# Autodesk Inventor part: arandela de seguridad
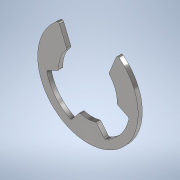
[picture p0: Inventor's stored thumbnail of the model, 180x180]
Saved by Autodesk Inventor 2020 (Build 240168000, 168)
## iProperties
Created: 2022-02
Part Number: arandela de seguridad
Material: Acero, alta resistencia, aleación baja
Document SubType Name: Modeling
Designer: Eresthor
Density: 7.85 g/cm^3
Appearance: Acero - Pulido
Author: Eresthor
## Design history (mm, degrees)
sketch "Boceto1"
  geometry: L1 (-1.903, -4.463)-(-1.083, -3.456); L2 (1.903, -4.463)-(1.083, -3.456); L3 (-2.549, 2.569)-(-3.401, 4.635); L4 (2.549, 2.569)-(3.401, 4.635); L5 (-4.775, -0.858)-(-3.61, -0.284); L6 (4.775, -0.858)-(3.61, -0.284); A1 r 6 centre (0, 0) between (-3.71, 4.715) and (3.71, 4.715); A2 r 3.5 centre (0, 0) between (-0.877, -3.388) and (0.877, -3.388); A3 r 3.5 centre (0, 0) between (3.499, -0.099) and (2.586, 2.358); A4 r 3.5 centre (0, 0) between (-2.586, 2.358) and (-3.499, -0.099); A5 r 5 centre (0, 0) between (2.143, -4.517) and (4.882, -1.081); A6 r 5 centre (0, 0) between (-4.882, -1.081) and (-2.143, -4.517); A7 r 0.2 centre (-3.586, 4.558) between (-3.401, 4.635) and (-3.71, 4.715); A8 r 0.2 centre (3.586, 4.558) between (3.71, 4.715) and (3.401, 4.635); A9 r 0.2 centre (2.734, 2.493) between (2.549, 2.569) and (2.586, 2.358); A10 r 0.2 centre (-2.734, 2.493) between (-2.586, 2.358) and (-2.549, 2.569); A11 r 0.2 centre (-3.699, -0.104) between (-3.61, -0.284) and (-3.499, -0.099); A12 r 0.2 centre (3.699, -0.104) between (3.499, -0.099) and (3.61, -0.284); A13 r 0.2 centre (4.687, -1.037) between (4.882, -1.081) and (4.775, -0.858); A14 r 0.2 centre (2.058, -4.337) between (1.903, -4.463) and (2.143, -4.517); A15 r 0.2 centre (0.928, -3.582) between (1.083, -3.456) and (0.877, -3.388); A16 r 0.2 centre (-0.928, -3.582) between (-0.877, -3.388) and (-1.083, -3.456); A17 r 0.2 centre (-2.058, -4.337) between (-2.143, -4.517) and (-1.903, -4.463); A18 r 0.2 centre (-4.687, -1.037) between (-4.775, -0.858) and (-4.882, -1.081); 12 further points
  constraints: 48 point on circle, 24 tangent, 18 centre point, 12 end point, 12 point on line, 11 equal radius, 1 coincident
extrude "Extrusión1" new body sketch "Boceto1" distance "d14" = 0.5; taper "d15" = 0 deg
node "Sólido1"
other parameters: "d4" = 1
